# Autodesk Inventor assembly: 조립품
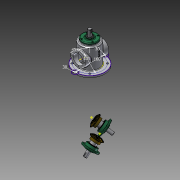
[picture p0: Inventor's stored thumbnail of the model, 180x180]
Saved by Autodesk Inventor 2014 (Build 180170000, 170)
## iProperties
Created: 2018-04
Part Number: 조립품
Document SubType Name: Assembly
Designer: NET
Author: NET
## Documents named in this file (14)
- C:\Users\NET\Desktop\480407V1012\조립품.iam
- C:\Users\NET\Desktop\480407V1012\본체.ipt
- C:\Users\NET\Desktop\480407V1012\메인 축.ipt
- 메인 축.ipt
- C:\Users\NET\Desktop\480407V1012\서브 축.ipt
- 서브 축.ipt
- C:\Users\NET\Desktop\480407V1012\베어링 6203.ipt
- C:\Users\NET\Desktop\480407V1012\서브 베벨기어.ipt
- C:\Users\NET\Desktop\480407V1012\메인 베벨기어.ipt
- C:\Users\NET\Desktop\480407V1012\키 4x4.ipt
- C:\Users\NET\Desktop\480407V1012\키 5x5.ipt
- C:\Users\NET\Desktop\480407V1012\커버.ipt
- C:\Users\NET\Desktop\480407V1012\오일 실.ipt
- 오일 실.ipt
